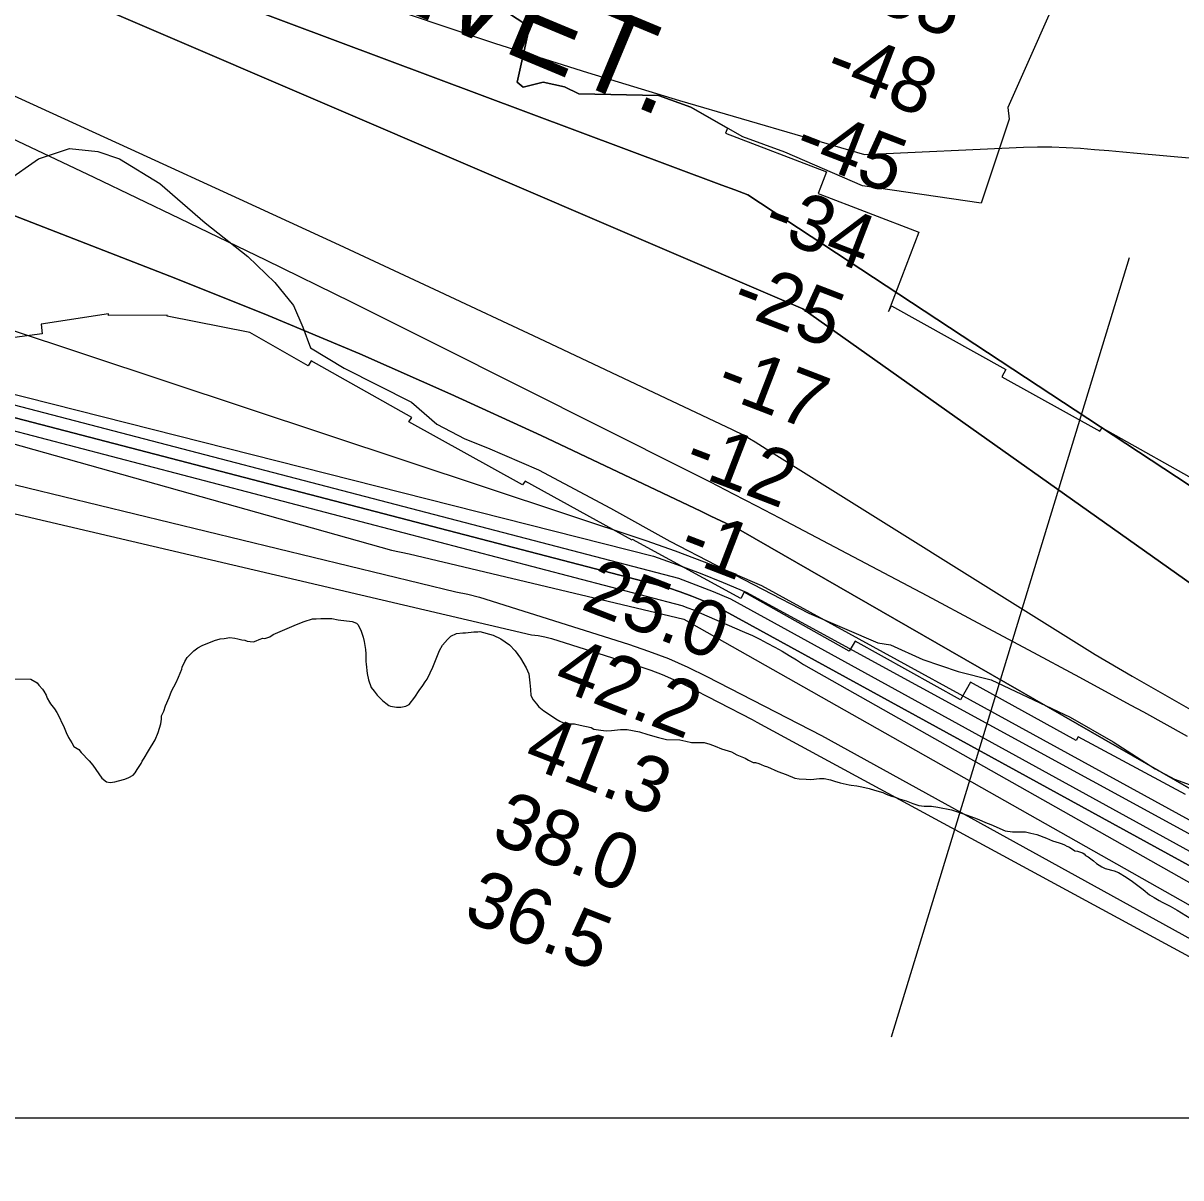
# Model space of a CAD drawing. Extents: x 3263578 to 3301413, y 764927 to 798602.
# Drawn here: x 3281950 to 3283343, y 781817 to 783206 of the extents above; entities that cross this region are included whole.
import ezdxf

# ---------------------------------------------------------------- set-up
doc = ezdxf.new("R2010")
doc.units = 0
for name, color, linetype in [('V-GRID-MAJR', 7, 'Continuous'), ('V-RIVR-EDGE', 7, 'Continuous'), ('V-RIVR-RANG', 7, 'Continuous'), ('V-RRAP-RVMT', 7, 'Continuous'), ('V-RRAP-RVMT-IDEN', 7, 'Continuous'), ('V-SITE-VEGE', 7, 'Continuous'), ('V-TOPO-DPTH', 7, 'Continuous'), ('V-TOPO-MAJR', 7, 'Continuous'), ('V-TOPO-MINR', 7, 'Continuous'), ('V-TOPO-WATR', 7, 'Continuous')]:
    doc.layers.add(name, color=color, linetype=linetype)

msp = doc.modelspace()

# ---------------------------------------------------------------- linework, layer by layer
at = {"layer": 'V-GRID-MAJR'}
msp.add_spline([(3267730.5, 781891.4), (3270351, 781890.6), (3275592.2, 781889.4), (3280833.3, 781889.1), (3286074.5, 781889.4), (3291315.6, 781890.6), (3296556.8, 781892.5), (3299177.4, 781893.7)], degree=3, dxfattribs=at)
at = {"layer": 'V-RIVR-EDGE'}
for points in [[(3281968.3, 783042.9), (3282005.7, 783055.4), (3282039.6, 783051.9), (3282065.7, 783043.1), (3282114.3, 783013.4), (3282169, 782965.9), (3282220.2, 782925.4), (3282252.7, 782894), (3282275.2, 782866.6), (3282286.4, 782840.5), (3282295.5, 782815.7), (3282335.9, 782791.2), (3282417.1, 782750.2), (3282447.4, 782723.6), (3282481.3, 782706.1), (3282508.6, 782695.2), (3282569.9, 782668.9), (3282656.3, 782622.6), (3282727.9, 782582.9), (3282895, 782496.4), (3282978, 782460.6), (3282993.2, 782458.4), (3283032.2, 782440.4), (3283074.8, 782426), (3283114.3, 782416.3), (3283209.4, 782371.3), (3283261.1, 782341.6), (3283311.8, 782308.9), (3283334.9, 782296.7), (3283384.8, 782278.7)], [(3281929.6, 783015.6), (3281968.3, 783042.9)]]:
    msp.add_lwpolyline(points, dxfattribs=at)
at = {"layer": 'V-RIVR-RANG'}
msp.add_line((3282994.7, 781986.8), (3283280.8, 782924.1), dxfattribs=at)
at = {"layer": 'V-RRAP-RVMT'}
for points in [[(3282489.6, 783855.9), (3282568.1, 783816.8), (3282573.8, 783828.9), (3282705.5, 783760.7), (3282694.6, 783739), (3282733.7, 783720.6), (3282712.1, 783676.3), (3282788.6, 783639.4), (3282798.4, 783661.9), (3282921, 783610.7), (3282928.7, 783626.1), (3283026.3, 783581.4), (3283020.4, 783568.5), (3283171.4, 783505.3), (3283174.3, 783512.9), (3283285.4, 783468), (3283209.3, 783274), (3283134.3, 783104.8)], [(3282201.7, 783372.3), (3282339.6, 783348.1), (3282339.1, 783345.5), (3282430.2, 783329.3), (3282443.4, 783301.6), (3282503, 783248.8), (3282498.4, 783241.6), (3282559, 783201.9), (3282544.1, 783135.2), (3282551.3, 783129.1), (3282575.4, 783135.2), (3282601.3, 783129.6), (3282618.4, 783121.2), (3282714, 783119.2), (3282752.9, 783105), (3282797.1, 783079.9), (3282794.8, 783073.9), (3282916.2, 783027.3), (3282906.1, 783001.2), (3283027.4, 782954.6)], [(3283134.3, 783104.8), (3283136.1, 783090.5), (3283102.2, 782989.6), (3282959.5, 783010.4), (3282866, 783051.1), (3282815.5, 783069.4), (3282752.9, 783105), (3282714, 783119.2), (3282618.4, 783121.2), (3282601.3, 783129.6), (3282575.4, 783135.2), (3282551.3, 783129.1), (3282544.1, 783135.2), (3282559, 783201.9), (3282498.4, 783241.6)], [(3283027.4, 782954.6), (3282990.8, 782859.1), (3282994.4, 782866.2), (3283132.1, 782789.4), (3283127.4, 782780.6), (3283245.2, 782715.2), (3283247.8, 782719.4), (3283375, 782647.9), (3283378, 782653), (3283513.8, 782577.2)], [(3283348.2, 782278), (3283219.2, 782347.4), (3283216.8, 782343), (3283089.6, 782413.5), (3283077.4, 782392.2), (3282950.8, 782462.6), (3282943.7, 782450.5), (3282817.1, 782521.4), (3282813.2, 782513.8), (3282683.1, 782585), (3282682.7, 782584.1), (3282553.9, 782655.3), (3282550.4, 782650.6), (3282413.8, 782726.4), (3282417.3, 782731.8), (3282296.2, 782799.9), (3282292.7, 782793.7), (3282222.4, 782834.1), (3282122.9, 782853.8), (3282123, 782855), (3282052.5, 782854.6), (3282052.4, 782856.5), (3281971.7, 782844.1), (3281972.6, 782832.4), (3281821.6, 782812.3)]]:
    msp.add_lwpolyline(points, dxfattribs=at)
at = {"layer": 'V-SITE-VEGE'}
for points in [[(3282112.4, 782352.8), (3282115.5, 782363.3), (3282116.1, 782368.6), (3282116.2, 782372.7), (3282119.2, 782378.6), (3282121.1, 782385), (3282125.4, 782395), (3282128.4, 782402.6), (3282133.9, 782413.1), (3282136.9, 782419.5), (3282140.6, 782428.9), (3282141.2, 782431.2), (3282144.3, 782438.2), (3282147.3, 782442.9), (3282151.5, 782447.6), (3282155, 782451), (3282159.8, 782454.5), (3282165.1, 782457.4), (3282180, 782463.6), (3282187, 782465.3), (3282191.8, 782465.8), (3282198.3, 782466.9), (3282204.7, 782466.2), (3282208.2, 782465.6), (3282212.9, 782464.3), (3282216.5, 782463.7), (3282219.4, 782462.5), (3282222.9, 782462.4), (3282227, 782461.8), (3282230, 782462.9), (3282233.6, 782464.6), (3282238.3, 782466.3), (3282240.6, 782465.7), (3282246.6, 782467.9), (3282250.7, 782470.8), (3282278.6, 782482.8), (3282288, 782486.2), (3282298.1, 782489.6), (3282302.2, 782489.5), (3282308.1, 782490), (3282311.1, 782489.9), (3282321.1, 782489.8), (3282328.7, 782488.5), (3282345.8, 782486.5), (3282351, 782484.1), (3282352.8, 782482.3), (3282353.9, 782479.3), (3282356.2, 782475.7), (3282359, 782467.5), (3282360.1, 782462.1), (3282361.7, 782452.7), (3282362.3, 782447.4), (3282362.1, 782438), (3282362.7, 782435), (3282363.7, 782423.8), (3282365.3, 782416.1), (3282368.7, 782406.7), (3282372.2, 782402.5), (3282375.7, 782397.7), (3282382, 782391.2), (3282386.1, 782388.1), (3282389.6, 782385.2), (3282391.9, 782384.5), (3282399, 782383.2), (3282404.3, 782383.2), (3282410.2, 782384.3), (3282414.3, 782386.6), (3282421, 782395.3), (3282426.4, 782403.4), (3282430.6, 782409.3), (3282433.6, 782413.9), (3282436, 782416.8), (3282439.6, 782424.5), (3282442.7, 782431.5), (3282450.6, 782451.4), (3282454.3, 782457.8), (3282460.3, 782464.8), (3282464.4, 782468.8), (3282471, 782471.7), (3282478.6, 782472.7), (3282482.2, 782472.7), (3282492.2, 782473.7), (3282496.9, 782473.7), (3282499.3, 782474.2), (3282515.1, 782469.8), (3282524.5, 782465.6), (3282534.9, 782458.4), (3282541.9, 782451.2), (3282548.3, 782442.3), (3282555.1, 782430.4), (3282558, 782423.3), (3282559.6, 782412.7), (3282560.1, 782404.4), (3282560.5, 782397.3), (3282563.4, 782392), (3282567.5, 782387.2), (3282570.4, 782383.7), (3282576.2, 782378.9), (3282582, 782375.2), (3282590.7, 782369.2), (3282595.4, 782366.2)], [(3281932.5, 782417.2), (3281959, 782416.8), (3281966.6, 782412.6), (3281968.9, 782409.6), (3281973, 782404.9), (3281974.7, 782402.5), (3281977.6, 782397.7), (3281978.7, 782394.2), (3281981.6, 782389.4), (3281982.7, 782387.1), (3281987.4, 782381.1), (3281990.2, 782376.9), (3281993.7, 782371), (3281996.5, 782364.5), (3281998.3, 782360.9), (3282001.7, 782352.6), (3282004.5, 782346.7), (3282008.5, 782340.2), (3282010.8, 782336), (3282016.7, 782332.4), (3282019.6, 782328.8), (3282029.4, 782318.6), (3282033.5, 782313.3), (3282044.4, 782297.8), (3282050.2, 782293.6), (3282054.4, 782292.4), (3282060.3, 782293.5), (3282064.4, 782294.6), (3282072.1, 782296.8), (3282076.8, 782298.5), (3282082.2, 782301.4), (3282084.6, 782304.3), (3282087, 782308.4), (3282091.8, 782315.4), (3282093, 782318.3), (3282095.4, 782321.8), (3282100.8, 782330.5), (3282108.7, 782344), (3282112.4, 782352.8)], [(3282595.4, 782366.2), (3282600.1, 782364.4), (3282604.2, 782363.1), (3282613, 782363), (3282620.1, 782361.7), (3282633, 782358.6), (3282636.5, 782356.8), (3282644.7, 782355.5), (3282651.2, 782354.8), (3282657.7, 782355.3), (3282668.3, 782356.3), (3282676.5, 782356.2), (3282691.2, 782353.6), (3282701.2, 782350.5), (3282714.1, 782346.8), (3282724, 782344.3), (3282739.9, 782344), (3282747, 782342.2), (3282754, 782340.9), (3282764.6, 782340.7), (3282769.3, 782340.7), (3282775.8, 782338.8), (3282782.2, 782336.3), (3282789.8, 782333.3), (3282802.1, 782329.6), (3282808.6, 782326), (3282818.5, 782321.7), (3282822.6, 782319.3), (3282827.9, 782316.8), (3282830.8, 782316.8), (3282834.9, 782315.6), (3282837.8, 782314.3), (3282841.3, 782312.5), (3282845.4, 782311.3), (3282857.7, 782305.8), (3282867.7, 782302.1), (3282878.2, 782297.8), (3282883.5, 782297.2), (3282891.7, 782296.5), (3282897.6, 782296.4), (3282907.7, 782297.4), (3282913.5, 782297.3), (3282921.2, 782296), (3282925.9, 782294.2), (3282932.9, 782292.3), (3282943.5, 782289.8), (3282945.8, 782289.2), (3282952.9, 782288.5), (3282958.7, 782287.2), (3282967.5, 782285.3), (3282974, 782283.5), (3282983.9, 782280.4), (3282988, 782278.5), (3282994.5, 782276.1), (3282999.2, 782274.8), (3283003.9, 782273), (3283012.1, 782270.5), (3283020.3, 782267.5), (3283027.3, 782265), (3283033.8, 782264.3), (3283042.6, 782264.2), (3283050.2, 782262.9), (3283066.7, 782259.7), (3283080.1, 782255.4), (3283094.2, 782249.9), (3283099.5, 782248), (3283107.7, 782244.4), (3283114.1, 782241.9), (3283131.1, 782234.6), (3283139.9, 782233.3), (3283147.5, 782233.2), (3283155.8, 782233.1), (3283162.2, 782231.8), (3283169.3, 782229.9), (3283181, 782225.6), (3283188, 782222.6), (3283196.2, 782220.1), (3283199.7, 782218.9), (3283202.7, 782217.7), (3283205.6, 782215.8), (3283208.5, 782214.6), (3283214.9, 782210.4), (3283218.4, 782209.8), (3283220.8, 782209.1), (3283224.3, 782207.9), (3283226.1, 782206.7), (3283227.8, 782204.9), (3283231.3, 782203.1), (3283237.7, 782198.3), (3283241.2, 782195.3), (3283247.6, 782191.1), (3283251.7, 782189.3), (3283262.3, 782186.2), (3283267.5, 782184.3), (3283276.9, 782178.9), (3283284.4, 782173.5), (3283297.2, 782163.8), (3283304.8, 782157.3), (3283310.7, 782154.2), (3283316.5, 782150.6), (3283320, 782148.8)], [(3283320, 782148.8), (3283325.8, 782145.8), (3283329.9, 782143.9), (3283338.1, 782139.1), (3283353.9, 782129.4)]]:
    msp.add_lwpolyline(points, dxfattribs=at)
at = {"layer": 'V-TOPO-DPTH'}
for points in [[(3283979.6, 782089.4), (3282888, 782862.5), (3281912.3, 783281), (3281651.6, 783366.2), (3281607.5, 783380.8), (3281563.5, 783395.7), (3281519.6, 783411.1), (3281475.8, 783426.8), (3281432.4, 783443.3), (3281389.4, 783460.7), (3281346.9, 783479.4), (3281304.8, 783499), (3280858.2, 783715.4)], [(3283979.6, 782089.4), (3282888, 782862.5), (3281912.3, 783281), (3281651.6, 783366.2), (3281607.5, 783380.8), (3281563.5, 783395.7), (3281519.6, 783411.1), (3281475.8, 783426.8), (3281432.4, 783443.3), (3281389.4, 783460.7), (3281346.9, 783479.4), (3281304.8, 783499), (3280858.2, 783715.4)], [(3283888.6, 781898.9), (3282782, 782505.4), (3282768.2, 782511.2), (3282754.3, 782516.7), (3282740.3, 782521.9), (3282726.2, 782526.9), (3281705.6, 782792.3), (3281690.7, 782798.6), (3281676, 782805.1), (3281661.5, 782812.2), (3281647.2, 782819.6), (3281449.7, 782925.5), (3281337.4, 782987.1), (3281225.9, 783050.2), (3281115.7, 783115.5), (3281006.4, 783182.2), (3280644.3, 783408)], [(3281374.9, 783366.2), (3281790.2, 783185.2), (3281819, 783172.6), (3281847.8, 783159.8), (3281876.5, 783146.9), (3281905.2, 783133.9), (3282089.2, 783050.1), (3282209.7, 782994.9), (3282330.1, 782939.4), (3282450.2, 782883.4), (3282570.2, 782827.1), (3282802.7, 782717.5), (3282816.8, 782710.3), (3282830.6, 782702.6), (3282843.8, 782694), (3283239.5, 782446.7), (3283284.2, 782420.6), (3283328.9, 782394.8), (3283373.8, 782369.1)], [(3281374.9, 783366.2), (3281790.2, 783185.2), (3281819, 783172.6), (3281847.8, 783159.8), (3281876.5, 783146.9), (3281905.2, 783133.9), (3282089.2, 783050.1), (3282209.7, 782994.9), (3282330.1, 782939.4), (3282450.2, 782883.4), (3282570.2, 782827.1), (3282802.7, 782717.5), (3282816.8, 782710.3), (3282830.6, 782702.6), (3282843.8, 782694), (3283239.5, 782446.7), (3283284.2, 782420.6), (3283328.9, 782394.8), (3283373.8, 782369.1)], [(3281977.8, 783315.5), (3282790.3, 783011.4), (3282806, 783005.6), (3282821.7, 782999.8), (3283853, 782321)], [(3283853, 782321), (3282821.7, 782999.8), (3282806, 783005.6), (3282790.3, 783011.4), (3281977.8, 783315.5)], [(3283823.3, 782015.1), (3282813.1, 782595.7), (3282801.1, 782601.6), (3282789.2, 782607.4), (3282777.2, 782613.2), (3282765.1, 782619), (3282572.9, 782709.9), (3282464.3, 782759.9), (3282354.9, 782808.3), (3282244.6, 782854.4), (3282133.6, 782898.9), (3281844.3, 783011.4)], [(3283823.3, 782015.1), (3282813.1, 782595.7), (3282801.1, 782601.6), (3282789.2, 782607.4), (3282777.2, 782613.2), (3282765.1, 782619), (3282572.9, 782709.9), (3282464.3, 782759.9), (3282354.9, 782808.3), (3282244.6, 782854.4), (3282133.6, 782898.9), (3281844.3, 783011.4)], [(3281742.3, 782809.7), (3282708, 782564.9), (3282736.1, 782554.9), (3282764.2, 782544.4), (3282791.9, 782533.3), (3282819.5, 782521.7), (3283856, 781956.5)], [(3281742.3, 782809.7), (3282708, 782564.9), (3282736.1, 782554.9), (3282764.2, 782544.4), (3282791.9, 782533.3), (3282819.5, 782521.7), (3283856, 781956.5)]]:
    msp.add_lwpolyline(points, dxfattribs=at)
at = {"layer": 'V-TOPO-MAJR'}
for points in [[(3280584.2, 783321.6), (3281089, 783022.7), (3281178.9, 782970.5), (3281269.4, 782919.5), (3281360.9, 782870.2), (3281453, 782822), (3281622.3, 782735.4), (3281630.3, 782731.4), (3281638.3, 782727.5), (3281646.4, 782723.8), (3281654.6, 782720.1), (3282470.3, 782522.1), (3282484.7, 782519.3), (3282498.9, 782515.6), (3282678.1, 782459.1), (3282702.2, 782450.8), (3282726.1, 782441.6), (3282749.4, 782431.3), (3282772.5, 782420.2), (3282910.4, 782349.3), (3283832, 781841.1)], [(3282408.4, 783218.8), (3282518.1, 783181.7), (3282628.6, 783146.8), (3282739.5, 783113.3), (3282962, 783048.3), (3283153.2, 783056.8), (3283170.3, 783057.3), (3283187.5, 783057.3), (3283204.6, 783056.7), (3283221.7, 783055.7), (3283238.8, 783054.3), (3283255.9, 783052.9), (3283272.9, 783051.4), (3283290, 783049.9), (3283463.9, 783034.2)]]:
    msp.add_lwpolyline(points, dxfattribs=at)
at = {"layer": 'V-TOPO-MINR'}
for points in [[(3280858.2, 783715.4), (3281304.8, 783499), (3281346.9, 783479.4), (3281389.4, 783460.7), (3281432.4, 783443.3), (3281475.8, 783426.8), (3281519.6, 783411.1), (3281563.5, 783395.7), (3281607.5, 783380.8), (3281651.6, 783366.2), (3281912.3, 783281), (3282888, 782862.5), (3283979.6, 782089.4)], [(3280700.9, 783489.4), (3280735.5, 783467.1), (3280782, 783437.9), (3280828.8, 783409.1), (3280876.1, 783381.3), (3280923.8, 783354), (3281707.7, 782914.5), (3281716.8, 782910), (3281726.1, 782906.2), (3281735.7, 782903.4), (3282698.9, 782583.9), (3282734.1, 782571.4), (3282769.1, 782558.2), (3282803.8, 782544.3), (3282838.2, 782529.8), (3283666.8, 782075.8)], [(3280672.4, 783448.4), (3280804, 783355.1), (3280897.8, 783289.9), (3280992.3, 783225.9), (3281088.1, 783163.7), (3281184.6, 783102.6), (3281293.8, 783035), (3281357.2, 782996.5), (3281421.1, 782958.8), (3281485.7, 782922.3), (3281550.7, 782886.6), (3281664.9, 782825.3), (3281673.2, 782821), (3281681.7, 782816.9), (3281690.3, 782813.1), (3281698.9, 782809.4), (3282738.2, 782538.4), (3282759.2, 782530.6), (3282780.1, 782522.2), (3282800.7, 782513.6), (3283832.9, 781945.9)], [(3280644.3, 783408), (3281006.4, 783182.2), (3281115.7, 783115.5), (3281225.9, 783050.2), (3281337.4, 782987.1), (3281449.7, 782925.5), (3281647.2, 782819.6), (3281661.5, 782812.2), (3281676, 782805.1), (3281690.7, 782798.6), (3281705.6, 782792.3), (3282726.2, 782526.9), (3282740.3, 782521.9), (3282754.3, 782516.7), (3282768.2, 782511.2), (3282782, 782505.4), (3283888.6, 781898.9)], [(3281374.9, 783366.2), (3281790.2, 783185.2), (3281819, 783172.6), (3281847.8, 783159.8), (3281876.5, 783146.9), (3281905.2, 783133.9), (3282089.2, 783050.1), (3282209.7, 782994.9), (3282330.1, 782939.4), (3282450.2, 782883.4), (3282570.2, 782827.1), (3282802.7, 782717.5), (3282816.8, 782710.3), (3282830.6, 782702.6), (3282843.8, 782694), (3283239.5, 782446.7), (3283284.2, 782420.6), (3283328.9, 782394.8), (3283373.8, 782369.1)], [(3280610, 783358.7), (3280657.9, 783326.6), (3280708, 783294.2), (3280758.7, 783262.9), (3280810.4, 783233.1), (3280862.7, 783204.3), (3281611.7, 782807.8), (3281638, 782794.4), (3281664.6, 782781.5), (3281691.6, 782769.6), (3282392.9, 782572.2), (3282414.3, 782567.9), (3282744.5, 782489.1), (3283892.6, 781840)], [(3281977.8, 783315.5), (3282790.3, 783011.4), (3282806, 783005.6), (3282821.7, 782999.8), (3283853, 782321)], [(3280896.7, 783218.1), (3281004.9, 783152.6), (3281114.8, 783089.8), (3281225.7, 783028.9), (3281629.5, 782813.7), (3281649.8, 782803.3), (3281670.3, 782793.4), (3281691.1, 782784.1), (3281712.2, 782775.2), (3282742.4, 782505.5), (3282749.4, 782502.9), (3282756.3, 782500.2), (3282763.2, 782497.3), (3282817.8, 782473.6), (3282827.1, 782469.4), (3282836.2, 782465.1), (3282845.1, 782460.4), (3282854, 782455.5), (3282862.8, 782450.5), (3282871.5, 782445.3), (3282880.2, 782440.1), (3282888.8, 782434.7), (3283887.7, 781870.4)], [(3281843.1, 783111.6), (3282034.8, 783020.7), (3282138.3, 782971.2), (3282241.5, 782921.3), (3282344.3, 782870.7), (3282447, 782819.6), (3282748.3, 782668.4), (3282776.3, 782654.3), (3282804.2, 782640), (3282832, 782625.6), (3282859.8, 782611), (3283036.9, 782517.4), (3283098.2, 782484.8), (3283159.5, 782452.1), (3283220.6, 782419.2), (3283281.7, 782386.1), (3283297.5, 782377.6), (3283350.3, 782348.3)], [(3281844.3, 783011.4), (3282133.6, 782898.9), (3282244.6, 782854.4), (3282354.9, 782808.3), (3282464.3, 782759.9), (3282572.9, 782709.9), (3282765.1, 782619), (3282777.2, 782613.2), (3282789.2, 782607.4), (3282801.1, 782601.6), (3282813.1, 782595.7), (3283823.3, 782015.1)], [(3281094.2, 782944.4), (3281579.5, 782719.8), (3281601.9, 782709.5), (3281624.4, 782699.3), (3281647, 782689.3), (3281669.6, 782679.4), (3282561.4, 782470.2), (3282569.5, 782469.5), (3282577.6, 782468), (3282585.5, 782465.9), (3282690.7, 782432.7), (3282704.8, 782427.9), (3282718.7, 782422.6), (3282732.4, 782416.6), (3282745.8, 782410.1), (3282827, 782368.3), (3282832.6, 782365.1), (3283843.9, 781816.9)]]:
    msp.add_lwpolyline(points, dxfattribs=at)
at = {"layer": 'V-TOPO-WATR'}
msp.add_lwpolyline([(3281742.3, 782809.7), (3282708, 782564.9), (3282736.1, 782554.9), (3282764.2, 782544.4), (3282791.9, 782533.3), (3282819.5, 782521.7), (3283856, 781956.5)], dxfattribs=at)

# ---------------------------------------------------------------- texts
at = {"layer": 'V-RIVR-RANG'}
for s, rotation, p in [('-55', 338.9253, (3282944.3, 783233.6)), ('-48', 338.9253, (3282911.2, 783139.2)), ('-45', 338.9253, (3282874.2, 783046.3)), ('-34', 338.9253, (3282836.4, 782953.7)), ('-25', 338.9253, (3282799.1, 782860.9)), ('-17', 338.9253, (3282780.3, 782760.9)), ('-12', 338.9253, (3282741.8, 782668.6)), ('-1', 338.9253, (3282735.5, 782563.9)), ('25.0', 338.7283, (3282619, 782502)), ('42.2', 338.7283, (3282585.7, 782407.7)), ('41.3', 338.7283, (3282549.6, 782314.4)), ('38.0', 338.7283, (3282510.9, 782222.2)), ('36.5', 338.7283, (3282477.5, 782127.9))]:
    msp.add_text(s, height=67, rotation=rotation, dxfattribs=at).set_placement(p)
at = {"layer": 'V-RRAP-RVMT-IDEN'}
msp.add_text('REVET.', height=100, rotation=337.3706, dxfattribs=at).set_placement((3282270.7, 783278.9))

doc.saveas('drawing.dxf')
